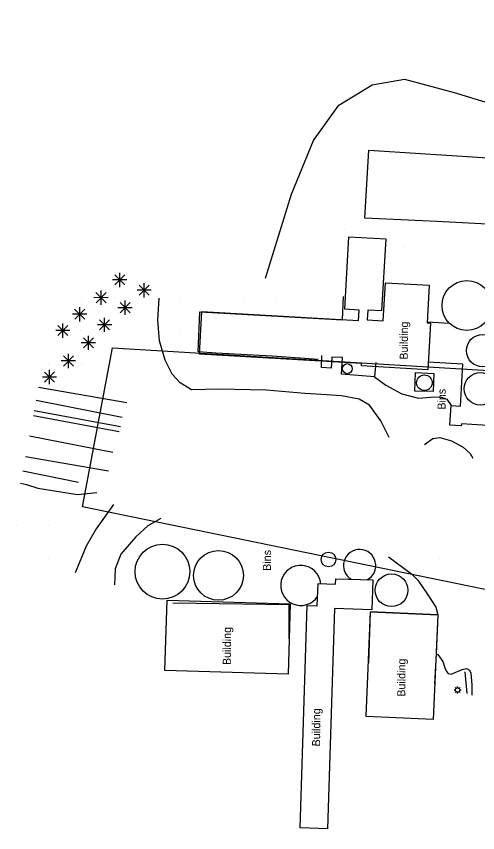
# Model space of a CAD drawing. Extents: x 19528164 to 19545171, y 7585743 to 7602745.
# Drawn here: x 19541400 to 19541683, y 7598916 to 7599418 of the extents above; entities that cross this region are included whole.
import ezdxf

# ---------------------------------------------------------------- set-up
doc = ezdxf.new("R2010")
doc.units = 0
for name, color, linetype in [('PhoAgStruc', 7, 'Continuous'), ('PhoBreakLine', 7, 'Continuous'), ('PhoBuilding', 7, 'Continuous'), ('PhoConcreteSlab', 7, 'Continuous'), ('PhoDrainageArrow', 7, 'Continuous'), ('PhoEdgeEntrancePaved', 7, 'Continuous'), ('PhoEdgeRoadGravel', 7, 'Continuous'), ('PhoISAEPoints', 7, 'Continuous'), ('PhoNotesDesign', 7, 'Continuous'), ('PhoSurveyLimits', 7, 'Continuous'), ('PhoVegetation', 7, 'Continuous'), ('SurBreakLine', 7, 'Continuous'), ('SurEdgeEntranceUnpaved', 7, 'Continuous'), ('SurNaturalCells', 7, 'Continuous'), ('SurROWRail', 7, 'Continuous')]:
    doc.layers.add(name, color=color, linetype=linetype)

msp = doc.modelspace()

# ---------------------------------------------------------------- linework, layer by layer
at = {"layer": 'PhoAgStruc'}
for centre, radius in [((19541676.63, 7599240.45), 15.31), ((19541686.32, 7599212.7), 9.96), ((19541603.18, 7599201.63), 3.08), ((19541684.85, 7599189.24), 9.96), ((19541650.52, 7599192.99), 4.8), ((19541489.7, 7599076.87), 16.82), ((19541524.07, 7599074.57), 15.28), ((19541591.65, 7599084.34), 4.52), ((19541630.34, 7599065.44), 10.04)]:
    msp.add_circle(centre, radius, dxfattribs=at)
for centre, radius, start, end in [((19541610.73, 7599080.58), 9.91, 298.5644, 237.7827), ((19541574.6, 7599068.42), 12.35, 4.7438, 326.9835)]:
    msp.add_arc(centre, radius, start, end, dxfattribs=at)
at = {"layer": 'PhoBreakLine'}
for p, q in [((19541467.92, 7599180.55), (19541413.69, 7599189.97)), ((19541463.96, 7599165.85), (19541411, 7599175.69)), ((19541459.29, 7599150.01), (19541408.08, 7599160.15)), ((19541438.21, 7599131.73), (19541404.02, 7599138.54))]:
    msp.add_line(p, q, dxfattribs=at)
for points in [[(19541599.64, 7599185.01), (19541587.38, 7599185.78), (19541577.01, 7599186.38), (19541553.5, 7599188.37), (19541524.39, 7599188.96), (19541507.59, 7599188.72), (19541500.49, 7599192.83), (19541495.67, 7599198.16), (19541491.38, 7599206.87), (19541487.86, 7599218.77), (19541486.93, 7599231.37), (19541487.62, 7599244.99)], [(19541585.35, 7599207.35), (19541557.12, 7599209.3), (19541522.54, 7599211.05), (19541511.64, 7599211.92), (19541512.67, 7599236.47), (19541563.92, 7599233.59), (19541600.2, 7599231.66), (19541600.94, 7599246.01)], [(19541402.65, 7599131.23), (19541406.22, 7599130.43), (19541413.14, 7599128.25), (19541437.47, 7599124.24), (19541449.38, 7599125.61)], [(19541496.07, 7599057.67), (19541567.25, 7599056.73), (19541567.23, 7599035.69)], [(19541658.76, 7599050.34), (19541617.14, 7599052.16), (19541616.17, 7599020.57)], [(19541658.76, 7599050.34), (19541657.67, 7599026.44), (19541656.75, 7599008.03)], [(19541675.34, 7599015.21), (19541676.52, 7599001.93)]]:
    msp.add_lwpolyline(points, dxfattribs=at)
at = {"layer": 'PhoBuilding'}
for points in [[(19541652.54, 7599200.97), (19541611.84, 7599203.29), (19541611.93, 7599204.85), (19541512.43, 7599210.52), (19541513.93, 7599236.72), (19541610.06, 7599231.23), (19541610.42, 7599237.64), (19541601.65, 7599238.14), (19541604.19, 7599282.68), (19541626.77, 7599281.4), (19541624.24, 7599237.08), (19541615.75, 7599237.57), (19541615.41, 7599231.62), (19541625.29, 7599231.05), (19541626.62, 7599254.41), (19541653.46, 7599252.87), (19541652.14, 7599229.77), (19541654.18, 7599229.65)], [(19541595.41, 7599054.22), (19541591.03, 7598918.9), (19541574.25, 7598919.43), (19541578.61, 7599056.04), (19541584.77, 7599055.84), (19541585.21, 7599069.5), (19541595.94, 7599069.16), (19541596.05, 7599072.5), (19541618.83, 7599071.77), (19541618.25, 7599053.49)], [(19541492.51, 7599059.41), (19541568.09, 7599057.12), (19541566.78, 7599013.82), (19541491.2, 7599016.1)], [(19541617.51, 7599052.1), (19541658.69, 7599050.34), (19541655.95, 7598986), (19541614.77, 7598987.76)]]:
    msp.add_lwpolyline(points, close=True, dxfattribs=at)
at = {"layer": 'PhoConcreteSlab'}
msp.add_lwpolyline([(19541620.6, 7599205.36), (19541619.95, 7599196.69), (19541599.69, 7599198.16), (19541600.16, 7599208.58), (19541593.6, 7599208.61), (19541593.25, 7599201.96), (19541587.43, 7599202.39), (19541587.55, 7599209.75)], dxfattribs=at)
msp.add_lwpolyline([(19541656.32, 7599198.57), (19541655.98, 7599187.54), (19541644.6, 7599187.83), (19541644.98, 7599199.21)], close=True, dxfattribs=at)
at = {"layer": 'PhoDrainageArrow'}
msp.add_line((19541464.87, 7599171.63), (19541412.19, 7599182.02), dxfattribs=at)
at = {"layer": 'PhoEdgeEntrancePaved'}
for points in [[(19541652.17, 7599230.31), (19541665.84, 7599229.6)], [(19541708.71, 7599165.53), (19541673.35, 7599167.82), (19541673.13, 7599166.42), (19541666.04, 7599166.89), (19541666.9, 7599179.06), (19541672.59, 7599178.67), (19541674.19, 7599204.32), (19541652.81, 7599205.58)]]:
    msp.add_lwpolyline(points, dxfattribs=at)
at = {"layer": 'PhoEdgeRoadGravel'}
for p, q in [((19541463.1, 7599162.87), (19541410.44, 7599172.69)), ((19541456.62, 7599138.6), (19541405.69, 7599147.42))]:
    msp.add_line(p, q, dxfattribs=at)
at = {"layer": 'PhoISAEPoints'}
for p, q in [((19541440, 7599245), (19541440, 7599245)), ((19541460, 7599245), (19541460, 7599245)), ((19541500, 7599245), (19541500, 7599245)), ((19541540, 7599245), (19541540, 7599245)), ((19541560, 7599245), (19541560, 7599245)), ((19541580, 7599245), (19541580, 7599245)), ((19541440, 7599225), (19541440, 7599225)), ((19541460, 7599225), (19541460, 7599225)), ((19541500, 7599225), (19541500, 7599225)), ((19541420, 7599205), (19541420, 7599205)), ((19541440, 7599205), (19541440, 7599205)), ((19541460, 7599205), (19541460, 7599205)), ((19541480, 7599205), (19541480, 7599205)), ((19541400, 7599105), (19541400, 7599105)), ((19541420, 7599105), (19541420, 7599105)), ((19541420, 7599085), (19541420, 7599085)), ((19541580, 7599085), (19541580, 7599085)), ((19541600, 7599085), (19541600, 7599085)), ((19541660, 7599085), (19541660, 7599085))]:
    msp.add_line(p, q, dxfattribs=at)
at = {"layer": 'PhoSurveyLimits'}
msp.add_lwpolyline([(19541832.46, 7597845.39), (19542376.97, 7598092.17), (19542113.78, 7598846.31), (19542039.74, 7598891.68), (19541786.93, 7599009.68), (19541786.81, 7599059.41), (19541708.63, 7599061.66), (19541440.61, 7599116.66), (19541458.99, 7599214.49), (19541802.13, 7599193.81), (19541861.6, 7599154.2), (19541900.69, 7599150.34), (19541983.87, 7599142.12), (19543859.55, 7599862.07), (19543863.55, 7599896.16), (19543904.76, 7600247.38), (19543914.92, 7600450.3), (19543927.42, 7600632.62), (19543934.84, 7600743.15), (19543933.97, 7600882.93)], dxfattribs=at)
at = {"layer": 'PhoVegetation'}
for p, q in [((19541466.56, 7599253.07), (19541460.37, 7599259.24)), ((19541466.55, 7599259.25), (19541460.38, 7599253.06)), ((19541463.47, 7599251.78), (19541463.46, 7599260.53)), ((19541467.84, 7599256.16), (19541459.09, 7599256.15)), ((19541463.47, 7599256.15), (19541463.47, 7599256.15)), ((19541478.47, 7599245.46), (19541478.46, 7599254.2)), ((19541452, 7599240.89), (19541451.99, 7599249.64)), ((19541482.84, 7599249.83), (19541474.09, 7599249.83)), ((19541481.56, 7599246.74), (19541475.37, 7599252.92)), ((19541481.55, 7599252.93), (19541475.38, 7599246.73)), ((19541478.46, 7599249.83), (19541478.46, 7599249.83)), ((19541456.37, 7599245.27), (19541447.62, 7599245.26)), ((19541455.09, 7599242.17), (19541448.9, 7599248.35)), ((19541455.08, 7599248.36), (19541448.91, 7599242.17)), ((19541452, 7599245.26), (19541452, 7599245.26)), ((19541438.9, 7599230.68), (19541438.89, 7599239.43)), ((19541471.11, 7599239.11), (19541462.36, 7599239.1)), ((19541469.83, 7599236.02), (19541463.64, 7599242.2)), ((19541469.83, 7599242.2), (19541463.65, 7599236.01)), ((19541466.74, 7599234.74), (19541466.73, 7599243.48)), ((19541466.74, 7599239.11), (19541466.74, 7599239.11)), ((19541443.27, 7599235.06), (19541434.52, 7599235.05)), ((19541441.99, 7599231.97), (19541435.8, 7599238.14)), ((19541441.99, 7599238.15), (19541435.81, 7599231.96)), ((19541438.9, 7599235.05), (19541438.9, 7599235.05)), ((19541428.55, 7599220.65), (19541428.54, 7599229.39)), ((19541457.25, 7599225.47), (19541451.06, 7599231.65)), ((19541457.24, 7599231.65), (19541451.07, 7599225.46)), ((19541454.16, 7599224.19), (19541454.15, 7599232.93)), ((19541432.91, 7599225.02), (19541424.17, 7599225.02)), ((19541431.63, 7599228.12), (19541425.45, 7599221.92)), ((19541431.64, 7599221.93), (19541425.45, 7599228.11)), ((19541428.54, 7599225.02), (19541428.54, 7599225.02)), ((19541458.53, 7599228.56), (19541449.78, 7599228.55)), ((19541454.15, 7599228.56), (19541454.15, 7599228.56)), ((19541447.32, 7599214.41), (19541441.13, 7599220.59)), ((19541447.32, 7599220.59), (19541441.14, 7599214.4)), ((19541444.23, 7599213.12), (19541444.22, 7599221.87)), ((19541448.6, 7599217.5), (19541439.85, 7599217.49)), ((19541444.23, 7599217.5), (19541444.23, 7599217.5)), ((19541435.08, 7599203.26), (19541428.89, 7599209.44)), ((19541435.08, 7599209.44), (19541428.9, 7599203.25)), ((19541431.99, 7599201.97), (19541431.98, 7599210.72)), ((19541436.36, 7599206.35), (19541427.61, 7599206.34)), ((19541431.99, 7599206.35), (19541431.99, 7599206.35)), ((19541423.44, 7599193.39), (19541417.25, 7599199.57)), ((19541423.43, 7599199.58), (19541417.26, 7599193.39)), ((19541420.35, 7599192.11), (19541420.34, 7599200.86)), ((19541424.72, 7599196.49), (19541415.97, 7599196.48)), ((19541420.35, 7599196.48), (19541420.35, 7599196.48))]:
    msp.add_line(p, q, dxfattribs=at)
at = {"layer": 'SurBreakLine'}
for points in [[(19541552.89, 7599257.18), (19541568.99, 7599308.86), (19541582.33, 7599341.92), (19541597.99, 7599363.5), (19541618.34, 7599376.13), (19541638.2, 7599379.64), (19541668.68, 7599371.35), (19541711.66, 7599358.25), (19541759.12, 7599355.39), (19541808.87, 7599354.27), (19541836.42, 7599345.57), (19541846.12, 7599323.84), (19541847.37, 7599294.48)], [(19541599.64, 7599185.01), (19541587.38, 7599185.78), (19541577.01, 7599186.38), (19541553.5, 7599188.37), (19541524.39, 7599188.96), (19541507.59, 7599188.72), (19541500.49, 7599192.83), (19541495.67, 7599198.16), (19541491.38, 7599206.87), (19541487.86, 7599218.77), (19541486.93, 7599231.37), (19541487.62, 7599244.99)], [(19541585.35, 7599207.35), (19541557.12, 7599209.3), (19541522.54, 7599211.05), (19541511.64, 7599211.92), (19541512.67, 7599236.47), (19541563.92, 7599233.59), (19541600.2, 7599231.66), (19541600.94, 7599246.01)], [(19541652.17, 7599230.31), (19541665.84, 7599229.6)]]:
    msp.add_lwpolyline(points, dxfattribs=at)
msp.add_lwpolyline([(19541813.63, 7599284.15), (19541732.13, 7599288.19), (19541658.22, 7599292.08), (19541613.98, 7599294.09), (19541616.39, 7599336.01), (19541692.81, 7599331), (19541760.01, 7599328.17), (19541816.47, 7599326.7)], close=True, dxfattribs=at)
at = {"layer": 'SurEdgeEntranceUnpaved'}
for p, q in [((19541601.38, 7599287.06), (19541601.38, 7599287.06)), ((19541637.6, 7599276.91), (19541637.6, 7599276.91)), ((19541540, 7599245), (19541540, 7599245)), ((19541560, 7599245), (19541560, 7599245)), ((19541580, 7599245), (19541580, 7599245)), ((19541653.26, 7599246.91), (19541653.26, 7599246.91)), ((19541500, 7599225), (19541500, 7599225))]:
    msp.add_line(p, q, dxfattribs=at)
at = {"layer": 'SurNaturalCells'}
for p, q in [((19541668.69, 7599004.15), (19541669.51, 7599004.16)), ((19541669.91, 7599005.12), (19541669.33, 7599005.69)), ((19541669.33, 7599002.62), (19541669.91, 7599003.19)), ((19541670.87, 7599005.52), (19541670.87, 7599006.33)), ((19541671.83, 7599005.12), (19541672.4, 7599005.7)), ((19541672.41, 7599002.62), (19541671.83, 7599003.2)), ((19541672.23, 7599004.16), (19541673.04, 7599004.16)), ((19541670.87, 7599001.98), (19541670.87, 7599002.8))]:
    msp.add_line(p, q, dxfattribs=at)
msp.add_circle((19541670.87, 7599004.16), 1.36, dxfattribs=at)
at = {"layer": 'SurROWRail'}
for points in [[(19541619.95, 7599196.69), (19541626.87, 7599191.58), (19541636.68, 7599186.07), (19541646.79, 7599183.59), (19541656.73, 7599184.34), (19541661.02, 7599184.17), (19541664.21, 7599182.91), (19541666.9, 7599179.06)], [(19541628.85, 7599159.35), (19541623.81, 7599169.49), (19541616.8, 7599179.16), (19541610.53, 7599182.92), (19541599.64, 7599185.01)], [(19541650.52, 7599155.02), (19541655.63, 7599158.7), (19541659.92, 7599159.4), (19541667.14, 7599157.31), (19541674.32, 7599153.29), (19541678.62, 7599149.44), (19541680.15, 7599146.69)], [(19541459.6, 7599118.19), (19541448.98, 7599103.13), (19541442.82, 7599092.62), (19541436.21, 7599076.16)], [(19541488.72, 7599109.61), (19541480.67, 7599104.97), (19541473.37, 7599098.31), (19541464.1, 7599087.62), (19541460.57, 7599078.69), (19541460.32, 7599068.71)], [(19541628.48, 7599086.06), (19541642.67, 7599075.44), (19541646.48, 7599071.73), (19541652.62, 7599062.54), (19541657.53, 7599055.02), (19541658.76, 7599050.34)], [(19541657.67, 7599026.44), (19541658.78, 7599025.88), (19541661.76, 7599021.63), (19541662.99, 7599017.78), (19541664.04, 7599015.42), (19541665.14, 7599014.2), (19541667.02, 7599013.81), (19541673.71, 7599016.75), (19541676.43, 7599017.36), (19541678.13, 7599016.4), (19541679.1, 7599014.52), (19541679.59, 7599007.3), (19541679.63, 7599000.96)]]:
    msp.add_lwpolyline(points, dxfattribs=at)

# ---------------------------------------------------------------- texts
at = {"layer": 'PhoNotesDesign'}
for s, p in [('Building', (19541640.27, 7599207.16)), ('Bins', (19541663.49, 7599176.42)), ('Bins', (19541556.26, 7599077.39)), ('Building', (19541531.62, 7599019.48)), ('Building', (19541638.73, 7599000.02)), ('Building', (19541586.46, 7598969.47))]:
    msp.add_text(s, height=4.92, rotation=89.5617, dxfattribs=at).set_placement(p)

doc.saveas('drawing.dxf')
